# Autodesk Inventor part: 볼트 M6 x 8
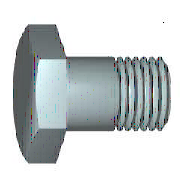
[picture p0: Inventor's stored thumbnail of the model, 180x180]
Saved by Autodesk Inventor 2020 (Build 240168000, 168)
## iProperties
Created: 2012-02
Part Number: 볼트 M6 x 8
Material: 강철, 연강
Description: 6각 머리 볼트 및 6각 머리 나사
Document SubType Name: Modeling
Standard: KS B 1002
Designer: mduedu
Standards Organization: KS
Language: ko-KR
Size Designation: C  M 6 x 12
Categories: <MemberInstance><Categories><Category DisplayName="조임쇠" InternalName="e4da775c-781d-43d5-af7c-5136215cf5a6" Mnemonic="FSTN"><Category DisplayName="볼트" InternalN
Density: 7.86 g/cm^3
Mass: 4.46616 g
Surface Area: 4.51243 cm^2
Volume: 0.568214 cm^3
Appearance: 강철
IsCustomPart: 1
Author: mduedu
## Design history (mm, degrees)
sketch "스케치1"
  geometry: L1 (0, 3)-(8, 3); L2 (8, 3)-(8, 0); L3 (8, 0)-(0, 0); L4 (-2.4, 0)-(14.4, 0) reference; L5 (0, -0.6)-(0, 3.6) reference; L6 (0, 3)-(0, 0)
  constraints: 8 end point, 3 point on line, 1 collinear
  dimensions: "d2" = 6 diameter of L1 L3 (= GD); "d59" = 8 distance between parallel lines of L2 L5 (= NLG)
revolve "본체" sketch "스케치1" stored, may be unused: angle "d12" = 90 deg
sketch "스케치2"
  geometry: L1 (0, 5.774)-(5, 2.887); L2 (5, 2.887)-(5, -2.887); L3 (5, -2.887)-(0, -5.774); L4 (0, -5.774)-(-5, -2.887); L5 (-5, -2.887)-(-5, 2.887); L6 (-5, 2.887)-(0, 5.774); L7 (-7, 0)-(7, 0) reference; L8 (0, 8.083)-(0, -8.083) reference; 2 further points
  constraints: 12 end point, 2 midpoint, 1 coincident, 1 vertical, 11 other
  dimensions: "d11" = 10 distance between parallel lines of L5 L2 (= SW)
extrude "머리" join sketch "스케치2" distance "d3" = 4 (= KOH); taper "d4" = 0 deg
revolve "모따기1" stored, may be unused: angle "d21" = 90 deg
workplane "Work Plane1"
body "Solid1"
feature "스레드" dims "d15" = 9 (= GEL), "d16" = 0
chamfer "모따기2" distance "d6" = 0.61345 (= -0.5 x SPD + 0.5 x GD); stored, may be unused: second distance "d7" = 0.61355 (computed from GUL), angle "d55" = 45 deg
sketch "스케치4"
  geometry: L1 (-3.423, 6)-(-4, 5); L2 (-1.1, 0)-(-0.234, 0); L3 (-4.753, 0)-(0.519, 0) reference; L4 (-4, 6)-(-3.423, 6); L5 (-4, 5)-(-4, 6); L6 (0, 7.2)-(0, -1.2) reference
  constraints: 8 end point, 1 parallel, 1 perpendicular, 1 point on line
  dimensions: "d65" = 10 diameter of L1.end L2 (= SW); "d67" = 30 deg angle of L1 L5 (= ANG1); "d68" = 12 diameter of L4 L2 (= 1.2 x SW); "d69" = 4 distance between parallel lines of L5 L6 (= KOH)
other parameters: "NLG" = 8 [user parameter; used in 1 equation term], "GD" = 6 (= NND) [user parameter; used in 2 equation terms], "BDM" = 6 (= NND) [user parameter], "KOH" = 4 [user parameter; used in 2 equation terms], "GEL" = 9 [user parameter; used in 1 equation term], "SW" = 10 [user parameter; used in 5 equation terms], "SPD" = 4.7731 (= NND - 1.2269 x PTC) [user parameter; used in 1 equation term], "SD2" = 6 (= NND) [user parameter], "SD" = 0 [user parameter], "ANG1" = 30 deg [user parameter; used in 1 equation term], "GAL" = 0.61345 (= 0.61345 x PTC) [user parameter], "GUL" = 0.61345 (= 0.61345 x PTC) [user parameter; used in 1 equation term], "d8" = 0, "RR" = 0.25 [user parameter], "d58" = 0, "RR1" = 0.1 [user parameter], "GD1" = 4.7731 (= THREADDIA - 1.2269 x PTC) [user parameter], "THREADDIA" = 6 [user parameter; used in 1 equation term], "TOA" = 30 deg [user parameter], "PTC" = 1 [user parameter; used in 5 equation terms], "NND" = 6 [user parameter; used in 4 equation terms], "E0" = 11.55 (= 1.155 x SW) [user parameter]
